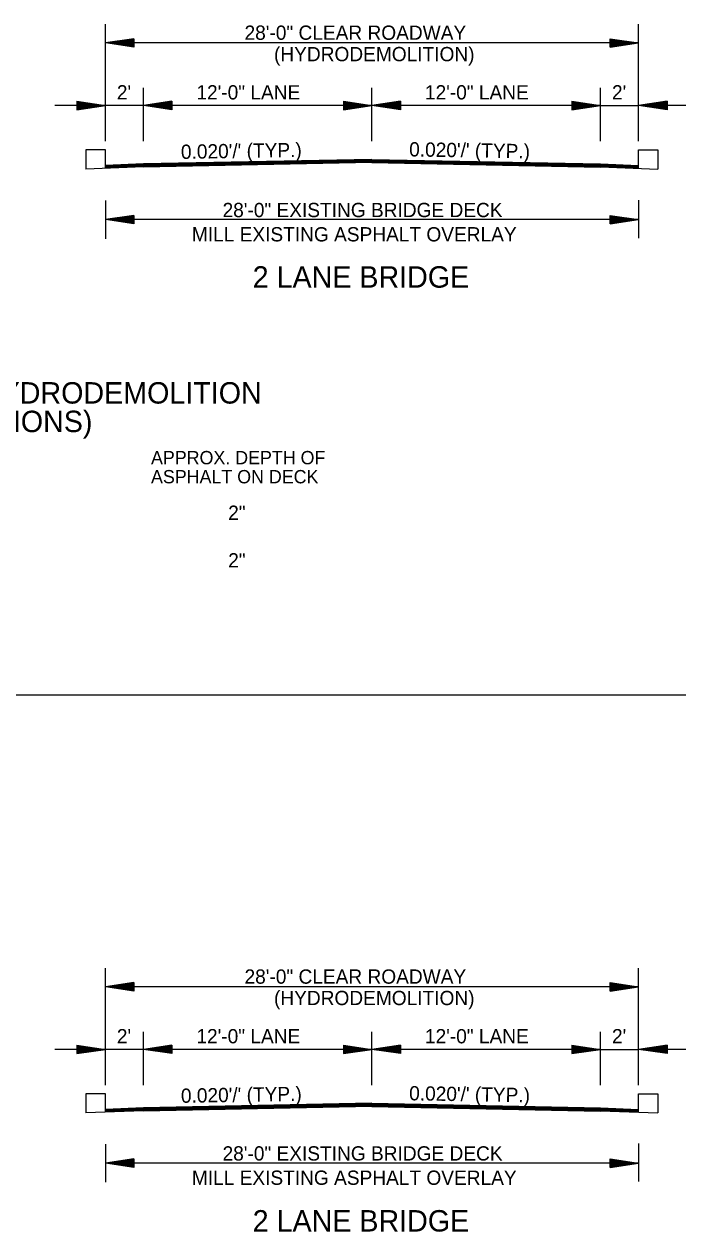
# Model space of a CAD drawing. Extents: x 549600 to 1930787, y -1955432 to 596640.
# Drawn here: x 551679 to 552023, y -1946446 to -1945811 of the extents above; entities that cross this region are included whole.
import ezdxf

# ---------------------------------------------------------------- set-up
doc = ezdxf.new("R2010")
doc.units = 0
for name, color, linetype in [('R_Border', 7, 'Continuous'), ('R_Border Notes', 7, 'Continuous'), ('S_AREA_CALC', 7, 'Continuous')]:
    doc.layers.add(name, color=color, linetype=linetype)

msp = doc.modelspace()

# ---------------------------------------------------------------- linework, layer by layer
at = {"layer": 'R_Border'}
for p, q in [((551711.85, -1945877.32), (551711.85, -1945887.44)), ((551722.02, -1945877.32), (551711.85, -1945877.32)), ((551722.02, -1945886.73), (551722.02, -1945877.32)), ((552002.02, -1945886.73), (552002.02, -1945877.32)), ((552002.02, -1945877.32), (552012.18, -1945877.32)), ((552012.18, -1945877.32), (552012.18, -1945887.44)), ((550992.91, -1946163.52), (552054.18, -1946163.52)), ((551711.85, -1946373.15), (551711.85, -1946383.26)), ((551722.02, -1946373.15), (551711.85, -1946373.15)), ((551722.02, -1946382.55), (551722.02, -1946373.15)), ((552002.02, -1946382.55), (552002.02, -1946373.15)), ((552002.02, -1946373.15), (552012.18, -1946373.15)), ((552012.18, -1946373.15), (552012.18, -1946383.26))]:
    msp.add_line(p, q, dxfattribs=at)
at = {"layer": 'S_AREA_CALC'}
for p, q in [((551722.02, -1945872.78), (551722.02, -1945811.29)), ((552002.02, -1945872.78), (552002.02, -1945811.29)), ((551737.02, -1945818.94), (551722.02, -1945821.19)), ((552002.02, -1945821.19), (551722.02, -1945821.19)), ((551737.02, -1945823.44), (551722.02, -1945821.19)), ((551737.02, -1945819.31), (551724.52, -1945821.19)), ((551737.02, -1945823.06), (551724.52, -1945821.19)), ((551737.02, -1945819.69), (551727.1, -1945821.19)), ((551737.02, -1945822.68), (551727.1, -1945821.19)), ((551737.02, -1945820.07), (551729.6, -1945821.19)), ((551737.02, -1945822.3), (551729.6, -1945821.19)), ((551737.02, -1945820.46), (551732.14, -1945821.19)), ((551737.02, -1945821.92), (551732.14, -1945821.19)), ((551737.02, -1945820.83), (551734.65, -1945821.19)), ((551737.02, -1945821.54), (551734.65, -1945821.19)), ((551737.02, -1945818.94), (551737.02, -1945823.44)), ((551987.02, -1945818.94), (552002.02, -1945821.19)), ((551987.02, -1945823.44), (551987.02, -1945818.94)), ((551987.02, -1945819.31), (551999.51, -1945821.19)), ((551987.02, -1945819.69), (551996.93, -1945821.19)), ((551987.02, -1945820.07), (551994.44, -1945821.19)), ((551987.02, -1945820.45), (551991.89, -1945821.19)), ((551987.02, -1945820.83), (551989.39, -1945821.19)), ((551987.02, -1945823.44), (552002.02, -1945821.19)), ((551987.02, -1945821.91), (551991.89, -1945821.19)), ((551987.02, -1945822.68), (551996.93, -1945821.19)), ((551987.02, -1945823.06), (551999.51, -1945821.19)), ((551987.02, -1945822.3), (551994.44, -1945821.19)), ((551987.02, -1945821.54), (551989.39, -1945821.19)), ((551742.02, -1945872.78), (551742.02, -1945844.83)), ((551862.02, -1945872.78), (551862.02, -1945844.83)), ((551982.02, -1945872.78), (551982.02, -1945844.83)), ((551707.02, -1945851.77), (551722.02, -1945854.02)), ((551707.02, -1945851.77), (551707.02, -1945856.27)), ((551707.02, -1945852.15), (551719.51, -1945854.02)), ((551707.02, -1945852.53), (551716.93, -1945854.02)), ((551707.02, -1945852.9), (551714.44, -1945854.02)), ((551707.02, -1945853.29), (551711.89, -1945854.02)), ((551757.02, -1945851.77), (551742.02, -1945854.02)), ((551757.02, -1945852.15), (551744.52, -1945854.02)), ((551757.02, -1945852.53), (551747.1, -1945854.02)), ((551757.02, -1945852.9), (551749.6, -1945854.02)), ((551757.02, -1945853.29), (551752.14, -1945854.02)), ((551757.02, -1945851.77), (551757.02, -1945856.27)), ((551847.02, -1945851.77), (551862.02, -1945854.02)), ((551847.02, -1945851.77), (551847.02, -1945856.27)), ((551847.02, -1945852.15), (551859.51, -1945854.02)), ((551847.02, -1945852.53), (551856.93, -1945854.02)), ((551847.02, -1945852.9), (551854.44, -1945854.02)), ((551847.02, -1945853.29), (551851.89, -1945854.02)), ((551877.02, -1945851.77), (551862.02, -1945854.02)), ((551877.02, -1945852.15), (551864.52, -1945854.02)), ((551877.02, -1945852.53), (551867.1, -1945854.02)), ((551877.02, -1945852.9), (551869.6, -1945854.02)), ((551877.02, -1945853.29), (551872.14, -1945854.02)), ((551877.02, -1945851.77), (551877.02, -1945856.27)), ((551967.02, -1945851.77), (551982.02, -1945854.02)), ((551967.02, -1945851.77), (551967.02, -1945856.27)), ((551967.02, -1945852.15), (551979.51, -1945854.02)), ((551967.02, -1945852.53), (551976.93, -1945854.02)), ((551967.02, -1945852.9), (551974.44, -1945854.02)), ((551967.02, -1945853.29), (551971.89, -1945854.02)), ((552017.02, -1945851.77), (552002.02, -1945854.02)), ((552017.02, -1945852.15), (552004.52, -1945854.02)), ((552017.02, -1945852.53), (552007.1, -1945854.02)), ((552017.02, -1945852.9), (552009.6, -1945854.02)), ((552017.02, -1945853.29), (552012.14, -1945854.02)), ((552017.02, -1945851.77), (552017.02, -1945856.27)), ((551722.02, -1945854.02), (551695.5, -1945854.02)), ((551707.02, -1945853.67), (551709.39, -1945854.02)), ((551707.02, -1945856.27), (551722.02, -1945854.02)), ((551707.02, -1945854.76), (551711.89, -1945854.02)), ((551707.02, -1945855.51), (551716.93, -1945854.02)), ((551707.02, -1945855.9), (551719.51, -1945854.02)), ((551707.02, -1945855.14), (551714.44, -1945854.02)), ((551707.02, -1945854.37), (551709.39, -1945854.02)), ((551742.02, -1945854.02), (551722.02, -1945854.02)), ((551862.02, -1945854.02), (551742.02, -1945854.02)), ((551757.02, -1945856.27), (551742.02, -1945854.02)), ((551757.02, -1945855.9), (551744.52, -1945854.02)), ((551757.02, -1945855.51), (551747.1, -1945854.02)), ((551757.02, -1945855.14), (551749.6, -1945854.02)), ((551757.02, -1945854.76), (551752.14, -1945854.02)), ((551757.02, -1945853.67), (551754.65, -1945854.02)), ((551757.02, -1945854.37), (551754.65, -1945854.02)), ((551847.02, -1945853.67), (551849.39, -1945854.02)), ((551847.02, -1945856.27), (551862.02, -1945854.02)), ((551847.02, -1945854.76), (551851.89, -1945854.02)), ((551847.02, -1945855.51), (551856.93, -1945854.02)), ((551847.02, -1945855.9), (551859.51, -1945854.02)), ((551847.02, -1945855.14), (551854.44, -1945854.02)), ((551847.02, -1945854.37), (551849.39, -1945854.02)), ((551982.02, -1945854.02), (551862.02, -1945854.02)), ((551877.02, -1945856.27), (551862.02, -1945854.02)), ((551877.02, -1945855.9), (551864.52, -1945854.02)), ((551877.02, -1945855.51), (551867.1, -1945854.02)), ((551877.02, -1945855.14), (551869.6, -1945854.02)), ((551877.02, -1945854.76), (551872.14, -1945854.02)), ((551877.02, -1945853.67), (551874.65, -1945854.02)), ((551877.02, -1945854.37), (551874.65, -1945854.02)), ((551967.02, -1945853.67), (551969.39, -1945854.02)), ((551967.02, -1945856.27), (551982.02, -1945854.02)), ((551967.02, -1945854.76), (551971.89, -1945854.02)), ((551967.02, -1945855.51), (551976.93, -1945854.02)), ((551967.02, -1945855.9), (551979.51, -1945854.02)), ((551967.02, -1945855.14), (551974.44, -1945854.02)), ((551967.02, -1945854.37), (551969.39, -1945854.02)), ((551982.02, -1945854.02), (552002.02, -1945854.02)), ((552017.02, -1945856.27), (552002.02, -1945854.02)), ((552028.54, -1945854.02), (552002.02, -1945854.02)), ((552017.02, -1945855.9), (552004.52, -1945854.02)), ((552017.02, -1945855.51), (552007.1, -1945854.02)), ((552017.02, -1945855.14), (552009.6, -1945854.02)), ((552017.02, -1945854.76), (552012.14, -1945854.02)), ((552017.02, -1945853.67), (552014.65, -1945854.02)), ((552017.02, -1945854.37), (552014.65, -1945854.02)), ((551742.02, -1945884.73), (551722.02, -1945885.53)), ((551862.02, -1945882.33), (551742.02, -1945884.73)), ((551862.02, -1945882.63), (551742.02, -1945885.03)), ((551862.02, -1945882.93), (551742.02, -1945885.33)), ((551862.02, -1945883.23), (551742.02, -1945885.63)), ((551862.02, -1945883.53), (551742.02, -1945885.93)), ((551862.02, -1945883.83), (551742.02, -1945886.23)), ((551862.02, -1945884), (551742.02, -1945886.4)), ((551862.02, -1945882.33), (551982.02, -1945884.73)), ((551862.02, -1945882.63), (551982.02, -1945885.03)), ((551862.02, -1945882.93), (551982.02, -1945885.33)), ((551862.02, -1945883.23), (551982.02, -1945885.63)), ((551862.02, -1945883.53), (551982.02, -1945885.93)), ((551862.02, -1945883.83), (551982.02, -1945886.23)), ((551862.02, -1945884), (551982.02, -1945886.4)), ((551982.02, -1945884.73), (552002.02, -1945885.53)), ((551742.02, -1945886.23), (551711.85, -1945887.44)), ((551742.02, -1945885.03), (551722.02, -1945885.83)), ((551742.02, -1945885.33), (551722.02, -1945886.13)), ((551742.02, -1945885.63), (551722.02, -1945886.43)), ((551742.02, -1945885.93), (551722.02, -1945886.73)), ((551982.02, -1945885.03), (552002.02, -1945885.83)), ((551982.02, -1945885.33), (552002.02, -1945886.13)), ((551982.02, -1945885.63), (552002.02, -1945886.43)), ((551982.02, -1945885.93), (552002.02, -1945886.73)), ((551982.02, -1945886.23), (552012.18, -1945887.44)), ((551722.02, -1945903.99), (551722.02, -1945923.99)), ((552002.02, -1945903.74), (552002.02, -1945923.74)), ((551737.02, -1945911.74), (551722.02, -1945913.99)), ((551737.02, -1945916.24), (551722.02, -1945913.99)), ((552002.02, -1945913.99), (551722.02, -1945913.99)), ((551737.02, -1945912.11), (551724.52, -1945913.99)), ((551737.02, -1945915.86), (551724.52, -1945913.99)), ((551737.02, -1945912.5), (551727.1, -1945913.99)), ((551737.02, -1945915.48), (551727.1, -1945913.99)), ((551737.02, -1945912.87), (551729.6, -1945913.99)), ((551737.02, -1945915.11), (551729.6, -1945913.99)), ((551737.02, -1945913.26), (551732.14, -1945913.99)), ((551737.02, -1945914.72), (551732.14, -1945913.99)), ((551737.02, -1945913.64), (551734.65, -1945913.99)), ((551737.02, -1945914.34), (551734.65, -1945913.99)), ((551737.02, -1945911.74), (551737.02, -1945916.24)), ((551987.02, -1945911.74), (552002.02, -1945913.99)), ((551987.02, -1945916.24), (551987.02, -1945911.74)), ((551987.02, -1945912.11), (551999.51, -1945913.99)), ((551987.02, -1945912.5), (551996.93, -1945913.99)), ((551987.02, -1945912.87), (551994.44, -1945913.99)), ((551987.02, -1945913.25), (551991.89, -1945913.99)), ((551987.02, -1945913.64), (551989.39, -1945913.99)), ((551987.02, -1945916.24), (552002.02, -1945913.99)), ((551987.02, -1945914.72), (551991.89, -1945913.99)), ((551987.02, -1945915.48), (551996.93, -1945913.99)), ((551987.02, -1945915.86), (551999.51, -1945913.99)), ((551987.02, -1945915.11), (551994.44, -1945913.99)), ((551987.02, -1945914.34), (551989.39, -1945913.99)), ((551722.02, -1946368.61), (551722.02, -1946307.12)), ((552002.02, -1946368.61), (552002.02, -1946307.12)), ((551737.02, -1946314.76), (551722.02, -1946317.01)), ((551737.02, -1946315.14), (551724.52, -1946317.01)), ((551737.02, -1946315.52), (551727.1, -1946317.01)), ((551737.02, -1946315.89), (551729.6, -1946317.01)), ((551737.02, -1946316.28), (551732.14, -1946317.01)), ((551737.02, -1946314.76), (551737.02, -1946319.26)), ((551987.02, -1946314.76), (552002.02, -1946317.01)), ((551987.02, -1946319.26), (551987.02, -1946314.76)), ((551987.02, -1946315.14), (551999.51, -1946317.01)), ((551987.02, -1946315.52), (551996.93, -1946317.01)), ((551987.02, -1946315.89), (551994.44, -1946317.01)), ((551987.02, -1946316.28), (551991.89, -1946317.01)), ((552002.02, -1946317.01), (551722.02, -1946317.01)), ((551737.02, -1946319.26), (551722.02, -1946317.01)), ((551737.02, -1946318.89), (551724.52, -1946317.01)), ((551737.02, -1946318.5), (551727.1, -1946317.01)), ((551737.02, -1946318.13), (551729.6, -1946317.01)), ((551737.02, -1946317.75), (551732.14, -1946317.01)), ((551737.02, -1946316.66), (551734.65, -1946317.01)), ((551737.02, -1946317.36), (551734.65, -1946317.01)), ((551987.02, -1946316.66), (551989.39, -1946317.01)), ((551987.02, -1946319.26), (552002.02, -1946317.01)), ((551987.02, -1946317.74), (551991.89, -1946317.01)), ((551987.02, -1946318.5), (551996.93, -1946317.01)), ((551987.02, -1946318.89), (551999.51, -1946317.01)), ((551987.02, -1946318.13), (551994.44, -1946317.01)), ((551987.02, -1946317.36), (551989.39, -1946317.01)), ((551742.02, -1946368.61), (551742.02, -1946340.66)), ((551862.02, -1946368.61), (551862.02, -1946340.66)), ((551982.02, -1946368.61), (551982.02, -1946340.66)), ((551707.02, -1946347.59), (551722.02, -1946349.84)), ((551707.02, -1946347.59), (551707.02, -1946352.09)), ((551707.02, -1946347.97), (551719.51, -1946349.84)), ((551757.02, -1946347.59), (551742.02, -1946349.84)), ((551757.02, -1946347.97), (551744.52, -1946349.84)), ((551757.02, -1946347.59), (551757.02, -1946352.09)), ((551847.02, -1946347.59), (551862.02, -1946349.84)), ((551847.02, -1946347.59), (551847.02, -1946352.09)), ((551847.02, -1946347.97), (551859.51, -1946349.84)), ((551877.02, -1946347.59), (551862.02, -1946349.84)), ((551877.02, -1946347.97), (551864.52, -1946349.84)), ((551877.02, -1946347.59), (551877.02, -1946352.09)), ((551967.02, -1946347.59), (551982.02, -1946349.84)), ((551967.02, -1946347.59), (551967.02, -1946352.09)), ((551967.02, -1946347.97), (551979.51, -1946349.84)), ((552017.02, -1946347.59), (552002.02, -1946349.84)), ((552017.02, -1946347.97), (552004.52, -1946349.84)), ((552017.02, -1946347.59), (552017.02, -1946352.09)), ((551722.02, -1946349.84), (551695.5, -1946349.84)), ((551707.02, -1946348.35), (551716.93, -1946349.84)), ((551707.02, -1946348.73), (551714.44, -1946349.84)), ((551707.02, -1946349.12), (551711.89, -1946349.84)), ((551707.02, -1946349.49), (551709.39, -1946349.84)), ((551707.02, -1946352.09), (551722.02, -1946349.84)), ((551707.02, -1946350.58), (551711.89, -1946349.84)), ((551707.02, -1946351.34), (551716.93, -1946349.84)), ((551707.02, -1946351.72), (551719.51, -1946349.84)), ((551707.02, -1946350.96), (551714.44, -1946349.84)), ((551707.02, -1946350.2), (551709.39, -1946349.84)), ((551742.02, -1946349.84), (551722.02, -1946349.84)), ((551862.02, -1946349.84), (551742.02, -1946349.84)), ((551757.02, -1946352.09), (551742.02, -1946349.84)), ((551757.02, -1946351.72), (551744.52, -1946349.84)), ((551757.02, -1946348.35), (551747.1, -1946349.84)), ((551757.02, -1946351.34), (551747.1, -1946349.84)), ((551757.02, -1946348.73), (551749.6, -1946349.84)), ((551757.02, -1946350.96), (551749.6, -1946349.84)), ((551757.02, -1946349.12), (551752.14, -1946349.84)), ((551757.02, -1946350.58), (551752.14, -1946349.84)), ((551757.02, -1946349.49), (551754.65, -1946349.84)), ((551757.02, -1946350.2), (551754.65, -1946349.84)), ((551847.02, -1946348.35), (551856.93, -1946349.84)), ((551847.02, -1946348.73), (551854.44, -1946349.84)), ((551847.02, -1946349.12), (551851.89, -1946349.84)), ((551847.02, -1946349.49), (551849.39, -1946349.84)), ((551847.02, -1946352.09), (551862.02, -1946349.84)), ((551847.02, -1946350.58), (551851.89, -1946349.84)), ((551847.02, -1946351.34), (551856.93, -1946349.84)), ((551847.02, -1946351.72), (551859.51, -1946349.84)), ((551847.02, -1946350.96), (551854.44, -1946349.84)), ((551847.02, -1946350.2), (551849.39, -1946349.84)), ((551982.02, -1946349.84), (551862.02, -1946349.84)), ((551877.02, -1946352.09), (551862.02, -1946349.84)), ((551877.02, -1946351.72), (551864.52, -1946349.84)), ((551877.02, -1946348.35), (551867.1, -1946349.84)), ((551877.02, -1946351.34), (551867.1, -1946349.84)), ((551877.02, -1946348.73), (551869.6, -1946349.84)), ((551877.02, -1946350.96), (551869.6, -1946349.84)), ((551877.02, -1946349.12), (551872.14, -1946349.84)), ((551877.02, -1946350.58), (551872.14, -1946349.84)), ((551877.02, -1946349.49), (551874.65, -1946349.84)), ((551877.02, -1946350.2), (551874.65, -1946349.84)), ((551967.02, -1946348.35), (551976.93, -1946349.84)), ((551967.02, -1946348.73), (551974.44, -1946349.84)), ((551967.02, -1946349.12), (551971.89, -1946349.84)), ((551967.02, -1946349.49), (551969.39, -1946349.84)), ((551967.02, -1946352.09), (551982.02, -1946349.84)), ((551967.02, -1946350.58), (551971.89, -1946349.84)), ((551967.02, -1946351.34), (551976.93, -1946349.84)), ((551967.02, -1946351.72), (551979.51, -1946349.84)), ((551967.02, -1946350.96), (551974.44, -1946349.84)), ((551967.02, -1946350.2), (551969.39, -1946349.84)), ((551982.02, -1946349.84), (552002.02, -1946349.84)), ((552017.02, -1946352.09), (552002.02, -1946349.84)), ((552028.54, -1946349.84), (552002.02, -1946349.84)), ((552017.02, -1946351.72), (552004.52, -1946349.84)), ((552017.02, -1946348.35), (552007.1, -1946349.84)), ((552017.02, -1946351.34), (552007.1, -1946349.84)), ((552017.02, -1946348.73), (552009.6, -1946349.84)), ((552017.02, -1946350.96), (552009.6, -1946349.84)), ((552017.02, -1946349.12), (552012.14, -1946349.84)), ((552017.02, -1946350.58), (552012.14, -1946349.84)), ((552017.02, -1946349.49), (552014.65, -1946349.84)), ((552017.02, -1946350.2), (552014.65, -1946349.84)), ((551862.02, -1946378.15), (551742.02, -1946380.55)), ((551862.02, -1946378.45), (551742.02, -1946380.85)), ((551862.02, -1946378.75), (551742.02, -1946381.15)), ((551862.02, -1946379.05), (551742.02, -1946381.45)), ((551862.02, -1946379.35), (551742.02, -1946381.75)), ((551862.02, -1946379.65), (551742.02, -1946382.05)), ((551862.02, -1946379.82), (551742.02, -1946382.22)), ((551862.02, -1946378.15), (551982.02, -1946380.55)), ((551862.02, -1946378.45), (551982.02, -1946380.85)), ((551862.02, -1946378.75), (551982.02, -1946381.15)), ((551862.02, -1946379.05), (551982.02, -1946381.45)), ((551862.02, -1946379.35), (551982.02, -1946381.75)), ((551862.02, -1946379.65), (551982.02, -1946382.05)), ((551862.02, -1946379.82), (551982.02, -1946382.22)), ((551742.02, -1946382.05), (551711.85, -1946383.26)), ((551742.02, -1946380.55), (551722.02, -1946381.35)), ((551742.02, -1946380.85), (551722.02, -1946381.65)), ((551742.02, -1946381.15), (551722.02, -1946381.95)), ((551742.02, -1946381.45), (551722.02, -1946382.25)), ((551742.02, -1946381.75), (551722.02, -1946382.55)), ((551982.02, -1946380.55), (552002.02, -1946381.35)), ((551982.02, -1946380.85), (552002.02, -1946381.65)), ((551982.02, -1946381.15), (552002.02, -1946381.95)), ((551982.02, -1946381.45), (552002.02, -1946382.25)), ((551982.02, -1946381.75), (552002.02, -1946382.55)), ((551982.02, -1946382.05), (552012.18, -1946383.26)), ((551722.02, -1946399.56), (551722.02, -1946419.56)), ((552002.02, -1946399.31), (552002.02, -1946419.31)), ((551737.02, -1946407.31), (551722.02, -1946409.56)), ((551737.02, -1946411.81), (551722.02, -1946409.56)), ((552002.02, -1946409.56), (551722.02, -1946409.56)), ((551737.02, -1946407.69), (551724.52, -1946409.56)), ((551737.02, -1946411.44), (551724.52, -1946409.56)), ((551737.02, -1946408.07), (551727.1, -1946409.56)), ((551737.02, -1946411.06), (551727.1, -1946409.56)), ((551737.02, -1946408.45), (551729.6, -1946409.56)), ((551737.02, -1946410.68), (551729.6, -1946409.56)), ((551737.02, -1946408.84), (551732.14, -1946409.56)), ((551737.02, -1946410.3), (551732.14, -1946409.56)), ((551737.02, -1946409.21), (551734.65, -1946409.56)), ((551737.02, -1946409.92), (551734.65, -1946409.56)), ((551737.02, -1946407.31), (551737.02, -1946411.81)), ((551987.02, -1946407.31), (552002.02, -1946409.56)), ((551987.02, -1946411.81), (551987.02, -1946407.31)), ((551987.02, -1946407.69), (551999.51, -1946409.56)), ((551987.02, -1946408.07), (551996.93, -1946409.56)), ((551987.02, -1946408.45), (551994.44, -1946409.56)), ((551987.02, -1946408.83), (551991.89, -1946409.56)), ((551987.02, -1946409.21), (551989.39, -1946409.56)), ((551987.02, -1946411.81), (552002.02, -1946409.56)), ((551987.02, -1946410.29), (551991.89, -1946409.56)), ((551987.02, -1946411.06), (551996.93, -1946409.56)), ((551987.02, -1946411.44), (551999.51, -1946409.56)), ((551987.02, -1946410.68), (551994.44, -1946409.56)), ((551987.02, -1946409.92), (551989.39, -1946409.56))]:
    msp.add_line(p, q, dxfattribs=at)

# ---------------------------------------------------------------- texts
at = {"layer": 'R_Border'}
for s, height, p in [('28 FT. CLEAR ROADWAY BRIDGE - HYDRODEMOLITION', 11.25, (551401.23, -1946010.6)), ('(ROADWAY TRANSITIONS)', 11.25, (551522.18, -1946025.6)), ('2"', 7.5, (551786.52, -1946071.69)), ('2"', 7.5, (551786.52, -1946096.69))]:
    msp.add_text(s, height=height, dxfattribs=at).set_placement(p)
at = {"layer": 'R_Border Notes'}
for s, p in [('APPROX. DEPTH OF', (551746, -1946042.5)), ('ASPHALT ON DECK', (551746, -1946052.5))]:
    msp.add_text(s, height=7, dxfattribs=at).set_placement(p)
at = {"layer": 'S_AREA_CALC'}
for s, height, p in [('28\'-0" CLEAR ROADWAY', 7.5, (551795.11, -1945819.52)), ('(HYDRODEMOLITION)', 7.5, (551810.58, -1945830.77)), ("2'", 7.5, (551728.06, -1945850.85)), ('12\'-0" LANE', 7.5, (551769.84, -1945850.85)), ('12\'-0" LANE', 7.5, (551889.84, -1945850.85)), ("2'", 7.5, (551988.06, -1945850.85)), ('28\'-0" EXISTING BRIDGE DECK', 7.5, (551783.57, -1945912.67)), ('MILL EXISTING ASPHALT OVERLAY', 7.5, (551767.44, -1945925.43)), ('2 LANE BRIDGE', 11.25, (551799.39, -1945949.71)), ('28\'-0" CLEAR ROADWAY', 7.5, (551795.11, -1946315.34)), ('(HYDRODEMOLITION)', 7.5, (551810.58, -1946326.59)), ("2'", 7.5, (551728.06, -1946346.67)), ('12\'-0" LANE', 7.5, (551769.84, -1946346.67)), ('12\'-0" LANE', 7.5, (551889.84, -1946346.67)), ("2'", 7.5, (551988.06, -1946346.67)), ('28\'-0" EXISTING BRIDGE DECK', 7.5, (551783.57, -1946408.24)), ('MILL EXISTING ASPHALT OVERLAY', 7.5, (551767.44, -1946421)), ('2 LANE BRIDGE', 11.25, (551799.39, -1946445.53))]:
    msp.add_text(s, height=height, dxfattribs=at).set_placement(p)
for rotation, p in [(0.97192, (551761.76, -1945882.12)), (359.02808, (551881.5, -1945880.75)), (0.97192, (551761.76, -1946377.95)), (359.02808, (551881.5, -1946376.58))]:
    msp.add_text("0.020'/' (TYP.)", height=7.5, rotation=rotation, dxfattribs=at).set_placement(p)

doc.saveas('drawing.dxf')
